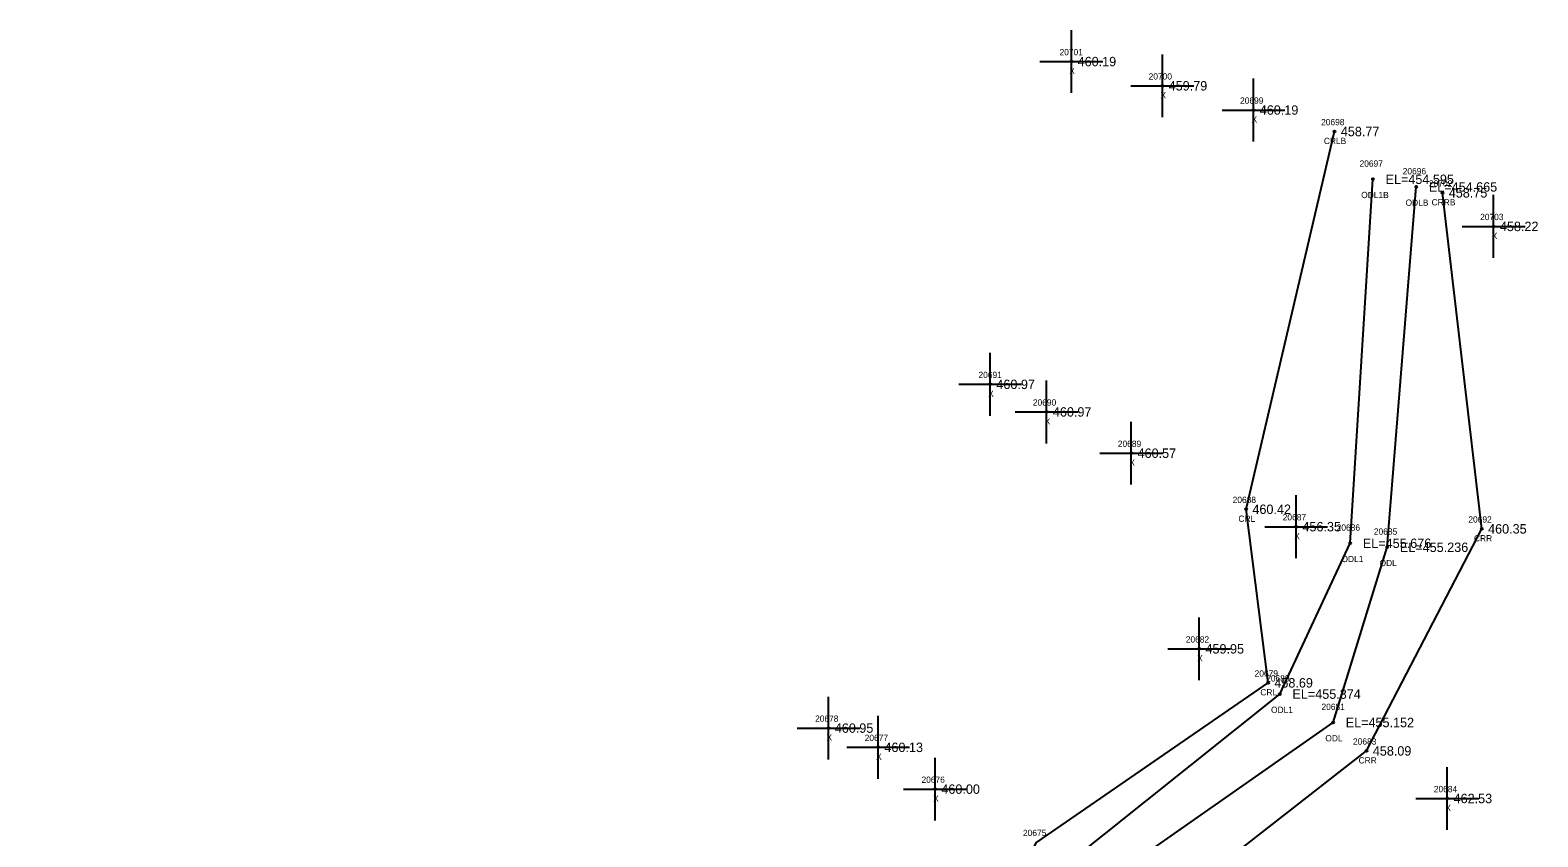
# Model space of a CAD drawing. Extents: x 1785066 to 1786589, y 770293 to 771312.
# Drawn here: x 1785796.9 to 1786036.9, y 771184 to 771312.4 of the extents above; entities that cross this region are included whole.
import ezdxf

# ---------------------------------------------------------------- set-up
doc = ezdxf.new("R2010")
doc.units = 0
for name, color, linetype in [('RD_EX_H2O', 7, 'Continuous'), ('RD_EX_H2O_txCode', 7, 'Continuous'), ('RD_EX_Misc', 7, 'Continuous'), ('RD_EX_Misc_txCode', 7, 'Continuous'), ('RD_EX_TX_H2O_ELEV', 7, 'Continuous'), ('RD_EX_TX_Misc_ELEV', 7, 'Continuous'), ('RD_SMD_Locator', 7, 'Continuous')]:
    doc.layers.add(name, color=color, linetype=linetype)

msp = doc.modelspace()

# ---------------------------------------------------------------- linework, layer by layer
at = {"layer": 'RD_EX_H2O'}
for points in [[(1785796.94, 770894.21), (1785817.52, 770934.08), (1785841.28, 770978.27), (1785905.84, 771069.13), (1785934.06, 771107.4), (1785932.74, 771138.87), (1785957.1, 771183.16), (1785993.97, 771208.54), (1785990.48, 771236.16), (1786004.55, 771296.27)], [(1785809.1, 770721.92), (1785797.13, 770787.08), (1785799.71, 770830.45), (1785797.84, 770854.32), (1785797.31, 770871.66), (1785799.74, 770882.87), (1785807.79, 770893.6), (1785824.76, 770932.46), (1785830, 770936.66), (1785845.12, 770978.01), (1785907.84, 771068.37), (1785939.25, 771107.77), (1785943.33, 771137.21), (1785960.57, 771178.58), (1785995.85, 771206.75), (1786007.06, 771230.75), (1786010.67, 771288.67)], [(1785820.66, 770730.64), (1785814.87, 770787.58), (1785810.48, 770814.19), (1785812.13, 770827.02), (1785814.82, 770830.33), (1785807.38, 770854.48), (1785804.49, 770870.81), (1785818.14, 770890.97), (1785834.56, 770929.05), (1785857.87, 770974.7), (1785917.08, 771062.46), (1785943.86, 771096.04), (1785952.84, 771134.11), (1785966.16, 771175.54), (1786004.33, 771202.23), (1786012.95, 771230.11), (1786017.56, 771287.45)], [(1785823.91, 770890.02), (1785840.03, 770925.86), (1785869.79, 770975.48), (1785920.39, 771060.62), (1785947.12, 771092.26), (1785958.51, 771131.14), (1785974.06, 771169.93), (1786009.64, 771197.71), (1786027.99, 771233.04), (1786021.73, 771286.51)]]:
    msp.add_lwpolyline(points, dxfattribs=at)
at = {"layer": 'RD_EX_Misc'}
for p, q in [((1785962.66, 771302.4), (1785962.66, 771312.4)), ((1785977.15, 771298.54), (1785977.15, 771308.54)), ((1785957.66, 771307.4), (1785967.66, 771307.4)), ((1785991.65, 771294.69), (1785991.65, 771304.69)), ((1785972.15, 771303.54), (1785982.15, 771303.54)), ((1785986.65, 771299.69), (1785996.65, 771299.69)), ((1786029.87, 771276.17), (1786029.87, 771286.17)), ((1786024.87, 771281.17), (1786034.87, 771281.17)), ((1785949.73, 771251.04), (1785949.73, 771261.04)), ((1785944.73, 771256.04), (1785954.73, 771256.04)), ((1785958.72, 771246.65), (1785958.72, 771256.65)), ((1785953.72, 771251.65), (1785963.72, 771251.65)), ((1785972.2, 771240.08), (1785972.2, 771250.08)), ((1785967.2, 771245.08), (1785977.2, 771245.08)), ((1785998.44, 771228.39), (1785998.44, 771238.39)), ((1785993.44, 771233.39), (1786003.44, 771233.39)), ((1785983.01, 771208.95), (1785983.01, 771218.95)), ((1785978.01, 771213.95), (1785988.01, 771213.95)), ((1785924.01, 771196.34), (1785924.01, 771206.34)), ((1785931.91, 771193.28), (1785931.91, 771203.28)), ((1785919.01, 771201.34), (1785929.01, 771201.34)), ((1785926.91, 771198.28), (1785936.91, 771198.28)), ((1785940.97, 771186.63), (1785940.97, 771196.63)), ((1786022.5, 771185.14), (1786022.5, 771195.14)), ((1785935.97, 771191.63), (1785945.97, 771191.63)), ((1786017.5, 771190.14), (1786027.5, 771190.14))]:
    msp.add_line(p, q, dxfattribs=at)
at = {"layer": 'RD_SMD_Locator'}
for centre in [(1785962.66, 771307.4), (1785977.15, 771303.54), (1785991.65, 771299.69), (1786004.55, 771296.27), (1786010.67, 771288.67), (1786017.56, 771287.45), (1786021.73, 771286.51), (1786029.87, 771281.17), (1785949.73, 771256.04), (1785958.72, 771251.65), (1785972.2, 771245.08), (1785990.48, 771236.16), (1785998.44, 771233.39), (1786027.99, 771233.04), (1786007.06, 771230.75), (1786012.95, 771230.11), (1785983.01, 771213.95), (1785993.97, 771208.54), (1785995.85, 771206.75), (1785924.01, 771201.34), (1786004.33, 771202.23), (1785931.91, 771198.28), (1786009.64, 771197.71), (1785940.97, 771191.63), (1786022.5, 771190.14)]:
    msp.add_circle(centre, 0.15, dxfattribs=at)

# ---------------------------------------------------------------- texts
at = {"layer": 'RD_EX_H2O_txCode'}
for s, p in [('20698', (1786002.41, 771297.27)), ('CRLB', (1786002.85, 771294.27)), ('20697', (1786008.53, 771290.67)), ('20696', (1786015.4, 771289.45)), ('20702', (1786019.57, 771287.51)), ('ODL1B', (1786008.79, 771285.67)), ('ODLB', (1786015.85, 771284.45)), ('CRRB', (1786020, 771284.51)), ('20688', (1785988.33, 771237.16)), ('CRL', (1785989.25, 771234.16)), ('20692', (1786025.85, 771234.04)), ('20686', (1786004.89, 771232.75)), ('20685', (1786010.81, 771232.11)), ('CRR', (1786026.74, 771231.04)), ('ODL1', (1786005.65, 771227.75)), ('ODL', (1786011.71, 771227.11)), ('20679', (1785991.83, 771209.54)), ('20680', (1785993.67, 771208.75)), ('CRL', (1785992.74, 771206.54)), ('20681', (1786002.47, 771204.23)), ('ODL1', (1785994.44, 771203.75)), ('ODL', (1786003.08, 771199.23)), ('20683', (1786007.49, 771198.71)), ('CRR', (1786008.38, 771195.71)), ('20675', (1785954.96, 771184.16))]:
    msp.add_text(s, height=1, dxfattribs=at).set_placement(p)
at = {"layer": 'RD_EX_Misc_txCode'}
for s, p in [('20701', (1785960.78, 771308.4)), ('X', (1785962.34, 771305.4)), ('20700', (1785974.96, 771304.54)), ('X', (1785976.84, 771301.54)), ('20699', (1785989.51, 771300.69)), ('X', (1785991.34, 771297.69)), ('20703', (1786027.72, 771282.17)), ('X', (1786029.56, 771279.17)), ('20691', (1785947.88, 771257.04)), ('X', (1785949.42, 771254.04)), ('20690', (1785956.54, 771252.65)), ('X', (1785958.41, 771249.65)), ('20689', (1785970.06, 771246.08)), ('X', (1785971.89, 771243.08)), ('20687', (1785996.3, 771234.39)), ('X', (1785998.13, 771231.39)), ('20682', (1785980.87, 771214.95)), ('X', (1785982.69, 771211.95)), ('20678', (1785921.87, 771202.34)), ('X', (1785923.69, 771199.34)), ('20677', (1785929.77, 771199.28)), ('X', (1785931.59, 771196.28)), ('20676', (1785938.81, 771192.63)), ('20684', (1786020.35, 771191.14)), ('X', (1785940.66, 771189.63)), ('X', (1786022.18, 771188.14))]:
    msp.add_text(s, height=1, dxfattribs=at).set_placement(p)
at = {"layer": 'RD_EX_TX_H2O_ELEV'}
for s, p in [('458.77', (1786005.55, 771295.52)), ('EL=454.595', (1786012.67, 771287.92)), ('EL=454.665', (1786019.56, 771286.7)), ('458.75', (1786022.73, 771285.76)), ('460.42', (1785991.48, 771235.41)), ('460.35', (1786028.99, 771232.29)), ('EL=455.676', (1786009.06, 771230)), ('EL=455.236', (1786014.95, 771229.36)), ('458.69', (1785994.97, 771207.79)), ('EL=455.374', (1785997.85, 771206)), ('EL=455.152', (1786006.33, 771201.48)), ('458.09', (1786010.64, 771196.96))]:
    msp.add_text(s, height=1.5, dxfattribs=at).set_placement(p)
at = {"layer": 'RD_EX_TX_Misc_ELEV'}
for s, p in [('460.19', (1785963.66, 771306.65)), ('459.79', (1785978.15, 771302.79)), ('460.19', (1785992.65, 771298.94)), ('458.22', (1786030.87, 771280.42)), ('460.97', (1785950.73, 771255.29)), ('460.97', (1785959.72, 771250.9)), ('460.57', (1785973.2, 771244.33)), ('456.35', (1785999.44, 771232.64)), ('459.95', (1785984.01, 771213.2)), ('460.95', (1785925.01, 771200.59)), ('460.13', (1785932.91, 771197.53)), ('460.00', (1785941.97, 771190.88)), ('462.53', (1786023.5, 771189.39))]:
    msp.add_text(s, height=1.5, dxfattribs=at).set_placement(p)

doc.saveas('drawing.dxf')
